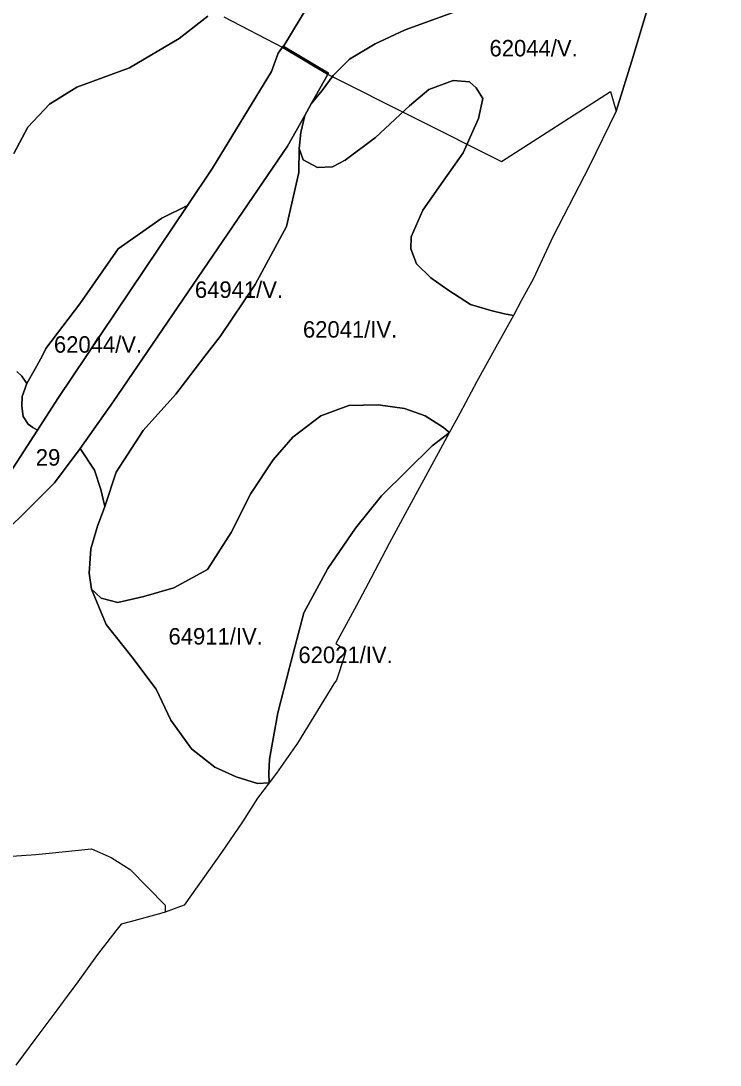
# Model space of a CAD drawing. Extents: x -521621 to -516761, y -1190184 to -1184927.
# Drawn here: x -517414 to -516777, y -1187885 to -1186934 of the extents above; entities that cross this region are included whole.
import ezdxf

# ---------------------------------------------------------------- set-up
doc = ezdxf.new("R2010")
doc.units = 0
doc.layers.add('BPEJ_s', color=7, linetype='Continuous')
doc.layers.add('odvodneni_s', color=7, linetype='Continuous')

msp = doc.modelspace()

# ---------------------------------------------------------------- linework, layer by layer
at = {"layer": 'BPEJ_s'}
for points in [[(-517003.71, -1186920.26), (-517063.94, -1186942.21), (-517091.49, -1186954.83), (-517114.83, -1186968.84), (-517129.77, -1186983.79), (-517139.58, -1186997.34), (-517149.58, -1187009.7), (-517133.86, -1186981.78), (-517175.27, -1186956.98), (-517179.84, -1186963.3), (-517185.8, -1186980.02), (-517239.52, -1187068.12), (-517262.4, -1187102.2), (-517285.6, -1187113.76), (-517325.49, -1187141.64), (-517360.32, -1187191.7), (-517391.35, -1187232.25), (-517394.62, -1187239.21), (-517400.89, -1187250.96), (-517408.54, -1187264.35), (-517413.18, -1187257.52), (-517417.55, -1187253.42)], [(-516844.56, -1186927.14), (-516850.39, -1186946.24), (-516856.6, -1186966.47), (-516871.88, -1187016.23), (-516896.58, -1187066.77), (-516929.39, -1187129.92), (-516947.5, -1187169.09), (-516958.34, -1187189), (-516965.57, -1187202.24), (-516973.59, -1187200.72), (-516985.93, -1187197.89), (-517004.64, -1187192.24), (-517025.1, -1187178.83), (-517040.63, -1187167.88), (-517053.69, -1187155.17), (-517058.98, -1187141.75), (-517058.63, -1187130.81), (-517048.04, -1187106.45), (-517029.39, -1187080.03), (-517011.18, -1187054.33), (-516997.18, -1187023.03), (-516993.44, -1187004.81), (-516999.51, -1186995), (-517005.58, -1186989.4), (-517020.52, -1186988.46), (-517042.46, -1186996.41), (-517060.21, -1187011.35), (-517091.02, -1187040.32), (-517118.57, -1187060.87), (-517130.24, -1187066.95), (-517143.78, -1187067.42), (-517156.85, -1187060.41), (-517160.59, -1187050.13), (-517159.18, -1187035.65), (-517155.41, -1187020.07), (-517149.58, -1187009.7), (-517139.58, -1186997.34), (-517129.77, -1186983.79), (-517114.83, -1186968.84), (-517091.49, -1186954.83), (-517063.94, -1186942.21), (-517003.71, -1186920.26)], [(-517420.48, -1187054.83), (-517407.81, -1187030.75), (-517388.08, -1187009.94), (-517362.97, -1186994.54), (-517315.17, -1186976.71), (-517269.81, -1186949.96), (-517243.89, -1186929.7)], [(-517243.89, -1186929.7), (-517269.81, -1186949.96), (-517315.17, -1186976.71), (-517362.97, -1186994.54), (-517388.08, -1187009.94), (-517407.81, -1187030.75), (-517420.48, -1187054.83)], [(-517510.08, -1187478.08), (-517399, -1187306.68), (-517380.36, -1187277.92), (-517262.4, -1187102.2), (-517239.52, -1187068.12), (-517185.8, -1186980.02), (-517179.84, -1186963.3), (-517175.27, -1186956.98), (-517133.86, -1186981.78), (-517149.58, -1187009.7), (-517155.41, -1187020.07), (-517171.29, -1187048.26), (-517329.96, -1187280.8), (-517359.97, -1187323.51), (-517383.4, -1187354.77), (-517451.95, -1187422.51)], [(-517417.55, -1187253.42), (-517413.18, -1187257.52), (-517408.54, -1187264.35), (-517412.91, -1187276.09), (-517413.18, -1187284.83), (-517411.82, -1187294.4), (-517407.45, -1187301.23), (-517403.08, -1187304.23), (-517399, -1187306.68), (-517510.08, -1187478.08)], [(-517451.95, -1187422.51), (-517383.4, -1187354.77), (-517359.97, -1187323.51), (-517347.02, -1187343.13), (-517341.32, -1187360.88), (-517337.52, -1187376.08), (-517344.35, -1187393.99), (-517350.37, -1187414.75), (-517351.71, -1187436.85), (-517349.7, -1187451.58), (-517336.32, -1187483.72), (-517312.9, -1187513.19), (-517290.81, -1187542.65), (-517277.43, -1187570.78), (-517258.69, -1187596.89), (-517237.27, -1187613.63), (-517217.87, -1187622.34), (-517198.46, -1187628.37), (-517187.86, -1187627.92), (-517198.48, -1187641.92), (-517212.07, -1187663.45), (-517231.42, -1187691.13), (-517265.45, -1187739.29), (-517274.3, -1187742.69), (-517282.67, -1187745.55), (-517285.67, -1187746.57), (-517314.62, -1187754.28), (-517322.71, -1187756.44), (-517327.54, -1187762.63), (-517335.84, -1187773.24), (-517341.31, -1187780.24), (-517345.01, -1187785.31), (-517353.59, -1187797.04), (-517362.24, -1187808.89), (-517371.78, -1187821.94), (-517375.37, -1187826.86), (-517381.27, -1187834.8), (-517391.15, -1187848.07), (-517401.26, -1187861.67), (-517411.5, -1187875.42), (-517418.52, -1187884.86)]]:
    msp.add_lwpolyline(points, dxfattribs=at)
for points in [[(-517349.7, -1187451.58), (-517351.71, -1187436.85), (-517350.37, -1187414.75), (-517344.35, -1187393.99), (-517337.52, -1187376.08), (-517327.39, -1187345.04), (-517302.7, -1187307.02), (-517272.93, -1187274.07), (-517246.46, -1187239.41), (-517232.41, -1187221.48), (-517200.74, -1187173.96), (-517172.25, -1187121.36), (-517161.05, -1187072.09), (-517160.59, -1187050.13), (-517156.85, -1187060.41), (-517143.78, -1187067.42), (-517130.24, -1187066.95), (-517118.57, -1187060.87), (-517091.02, -1187040.32), (-517060.21, -1187011.35), (-517042.46, -1186996.41), (-517020.52, -1186988.46), (-517005.58, -1186989.4), (-516999.51, -1186995), (-516993.44, -1187004.81), (-516997.18, -1187023.03), (-517011.18, -1187054.33), (-517029.39, -1187080.03), (-517048.04, -1187106.45), (-517058.63, -1187130.81), (-517058.98, -1187141.75), (-517053.69, -1187155.17), (-517040.63, -1187167.88), (-517025.1, -1187178.83), (-517004.64, -1187192.24), (-516985.93, -1187197.89), (-516973.59, -1187200.72), (-516965.57, -1187202.24), (-516981.42, -1187231.27), (-516998.89, -1187262.51), (-517014.39, -1187291.51), (-517024.06, -1187309.28), (-517024.84, -1187308.06), (-517029.14, -1187304.26), (-517045.87, -1187293.55), (-517064.61, -1187286.85), (-517088.71, -1187283.5), (-517115.47, -1187284.17), (-517140.91, -1187293.55), (-517166.34, -1187312.97), (-517184.41, -1187333.72), (-517204.48, -1187364.53), (-517222.55, -1187400.02), (-517243.97, -1187433.5), (-517274.75, -1187450.24), (-517302.19, -1187458.28), (-517325.61, -1187463.63), (-517341, -1187459.62)], [(-517359.97, -1187323.51), (-517329.96, -1187280.8), (-517171.29, -1187048.26), (-517155.41, -1187020.07), (-517159.18, -1187035.65), (-517160.59, -1187050.13), (-517161.05, -1187072.09), (-517172.25, -1187121.36), (-517200.74, -1187173.96), (-517232.41, -1187221.48), (-517246.46, -1187239.41), (-517272.93, -1187274.07), (-517302.7, -1187307.02), (-517327.39, -1187345.04), (-517337.52, -1187376.08), (-517341.32, -1187360.88), (-517347.02, -1187343.13)], [(-517408.54, -1187264.35), (-517400.89, -1187250.96), (-517394.62, -1187239.21), (-517391.35, -1187232.25), (-517360.32, -1187191.7), (-517325.49, -1187141.64), (-517285.6, -1187113.76), (-517262.4, -1187102.2), (-517380.36, -1187277.92), (-517399, -1187306.68), (-517403.08, -1187304.23), (-517407.45, -1187301.23), (-517411.82, -1187294.4), (-517413.18, -1187284.83), (-517412.91, -1187276.09)], [(-517349.7, -1187451.58), (-517341, -1187459.62), (-517325.61, -1187463.63), (-517302.19, -1187458.28), (-517274.75, -1187450.24), (-517243.97, -1187433.5), (-517222.55, -1187400.02), (-517204.48, -1187364.53), (-517184.41, -1187333.72), (-517166.34, -1187312.97), (-517140.91, -1187293.55), (-517115.47, -1187284.17), (-517088.71, -1187283.5), (-517064.61, -1187286.85), (-517045.87, -1187293.55), (-517029.14, -1187304.26), (-517024.84, -1187308.06), (-517024.06, -1187309.28), (-517039.43, -1187320.84), (-517085.49, -1187366.47), (-517109.43, -1187395.91), (-517134.4, -1187432.53), (-517156.28, -1187473.14), (-517169.51, -1187522.88), (-517180, -1187563.95), (-517187.75, -1187606.39), (-517188.2, -1187619.17), (-517187.86, -1187627.92), (-517198.46, -1187628.37), (-517217.87, -1187622.34), (-517237.27, -1187613.63), (-517258.69, -1187596.89), (-517277.43, -1187570.78), (-517290.81, -1187542.65), (-517312.9, -1187513.19), (-517336.32, -1187483.72)], [(-517187.86, -1187627.92), (-517188.2, -1187619.17), (-517187.75, -1187606.39), (-517180, -1187563.95), (-517169.51, -1187522.88), (-517156.28, -1187473.14), (-517134.4, -1187432.53), (-517109.43, -1187395.91), (-517085.49, -1187366.47), (-517039.43, -1187320.84), (-517024.06, -1187309.28), (-517038.01, -1187334.89), (-517060.45, -1187376.19), (-517068.28, -1187390.81), (-517078.57, -1187410.02), (-517095.03, -1187441.31), (-517108.3, -1187466.4), (-517127.2, -1187500.93), (-517117.98, -1187506.92), (-517119.44, -1187512.1), (-517126.72, -1187534.43), (-517128.98, -1187537.83), (-517162.09, -1187591.74), (-517181.17, -1187619.1)]]:
    msp.add_lwpolyline(points, close=True, dxfattribs=at)
at = {"layer": 'odvodneni_s'}
msp.add_lwpolyline([(-516954.83, -1186592.8), (-517175.45, -1186958.22), (-517134.87, -1186982.42), (-516976.29, -1187062.17), (-516877.08, -1186998.25), (-516871.88, -1187016.23), (-516856.6, -1186966.47), (-516850.39, -1186946.24), (-516844.56, -1186927.14), (-516822.77, -1186861.25), (-516803.7, -1186796.3), (-516791.41, -1186724.89), (-516777.29, -1186712.47), (-516783.52, -1186685.16), (-516792.51, -1186656.77), (-516821.91, -1186586.88)], close=True, dxfattribs=at)
for points in [[(-517229.06, -1186930.43), (-517175.45, -1186958.22), (-516954.83, -1186592.8)], [(-517430.92, -1187695.29), (-517400.34, -1187693.17), (-517388.28, -1187691.97), (-517349.59, -1187687.83), (-517331.9, -1187695.75), (-517314.4, -1187706.71), (-517282.72, -1187739.22), (-517282.67, -1187745.55), (-517285.67, -1187746.57), (-517314.62, -1187754.28), (-517322.71, -1187756.44), (-517327.54, -1187762.63), (-517335.84, -1187773.24), (-517341.31, -1187780.24), (-517345.01, -1187785.31), (-517353.59, -1187797.04), (-517362.24, -1187808.89), (-517371.78, -1187821.94), (-517375.37, -1187826.86), (-517381.27, -1187834.8), (-517391.15, -1187848.07), (-517401.26, -1187861.67), (-517411.5, -1187875.42), (-517418.52, -1187884.86)]]:
    msp.add_lwpolyline(points, dxfattribs=at)

# ---------------------------------------------------------------- texts
at = {"layer": 'BPEJ_s'}
for s, p in [('62044/V.', (-516987.27, -1186966.38)), ('64941/V.', (-517255.55, -1187186.25)), ('62041/IV.', (-517157.15, -1187222.46)), ('62044/V.', (-517383.92, -1187236.17)), ('29', (-517400.43, -1187339.02)), ('64911/IV.', (-517279.57, -1187501.92)), ('62021/IV.', (-517161.29, -1187518.78))]:
    msp.add_text(s, height=15, dxfattribs=at).set_placement(p)

doc.saveas('drawing.dxf')
